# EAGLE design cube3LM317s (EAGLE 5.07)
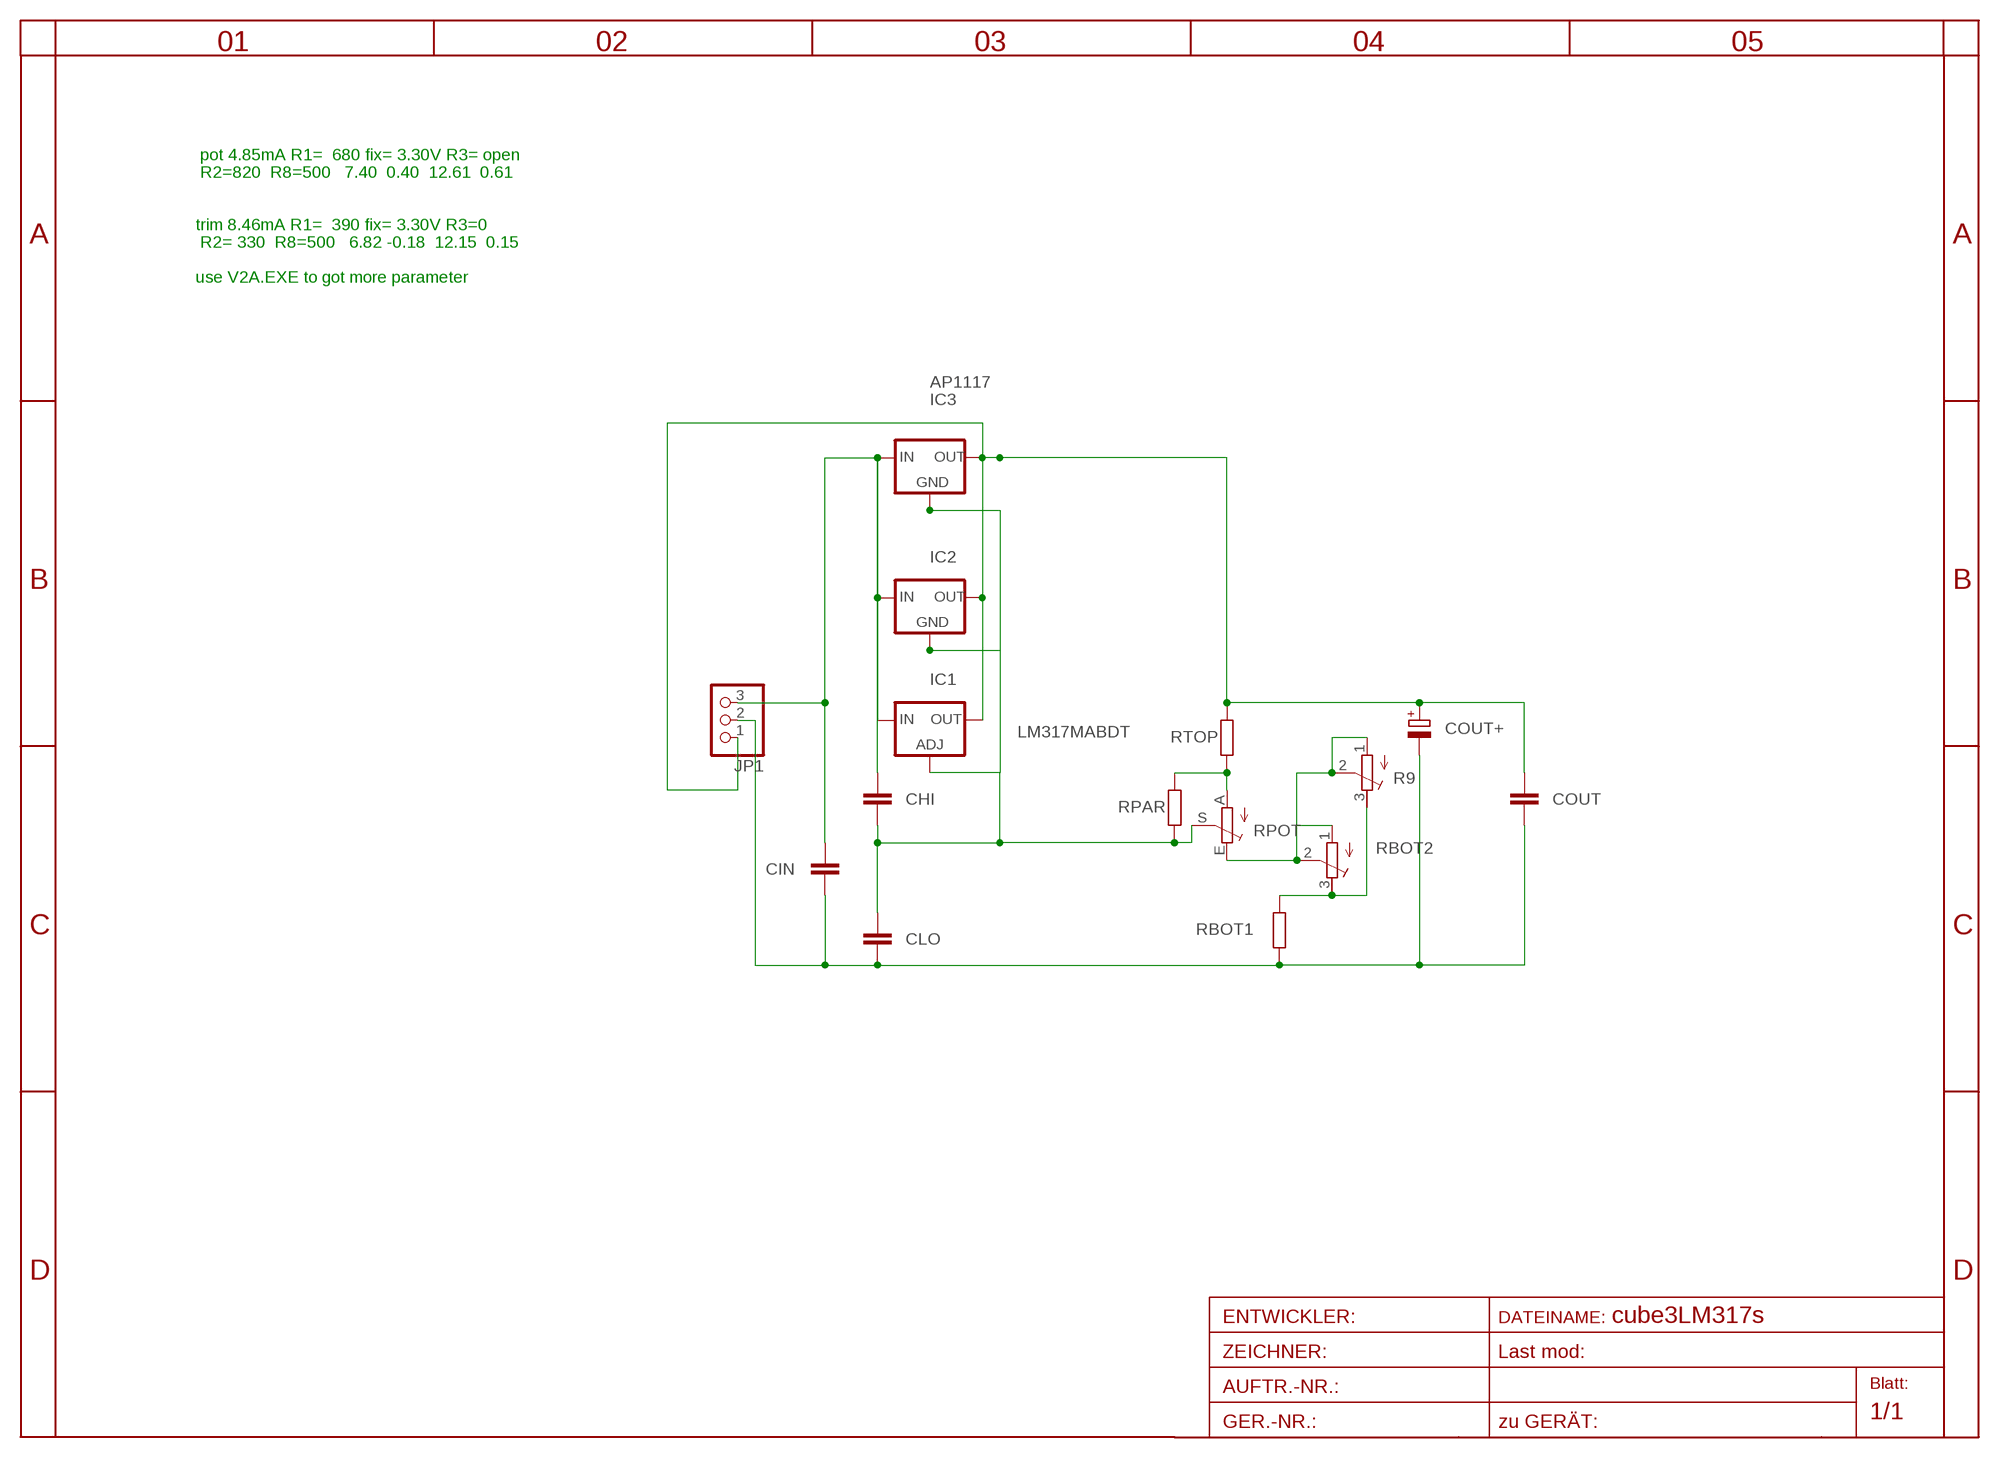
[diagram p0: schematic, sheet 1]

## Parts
CHI  C-EUC0805  [C0805]
CIN  C-EUC1206  [C1206]
CLO  C-EUC0805  [C0805]
COUT  C-EUC1206  [C1206]
COUT+  CPOL-EUE2.5-6  [E2,5-6]
IC1  LM317MABDT  [DPACK]
IC2  78XXS  [78XXS]
IC3  AP1117  [SOT223]
JP1  PINHD-1X3  [1X03]
R9  R-TRIMM3374  [RTRIM3374]
RBOT1  R-EU_R1206  [R1206]
RBOT2  R-TRIMM3202  [RTRIM3202]
RPAR  R-EU_R0603  [R0603]
RPOT  TRIM_EU-RAND160  [RANDL]
RTOP  R-EU_R0805  [R0805]

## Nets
GND: CIN.2 CLO.2 COUT+.- COUT.2 JP1.2 RBOT1.1
IN: CHI.1 CIN.1 IC1.3(IN) IC2.IN IC3.3(IN) JP1.3
N$1: R9.1(E) R9.2(S) RBOT2.1(E) RBOT2.2(S) RPOT.E
N$4: CHI.2 CLO.1 IC1.1(ADJ) IC2.GND IC3.1(GND) RPAR.1 RPOT.S
N$6: R9.3(A) RBOT1.2 RBOT2.3(A)
N$7: RPAR.2 RPOT.A RTOP.1
OUT: COUT+.+ COUT.1 IC1.4(OUT) IC2.OUT IC3.2(OUT) IC3.4(TAB) JP1.1 RTOP.2

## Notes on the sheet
- pot 4.85mA R1=  680 fix= 3.30V R3= open
- R2=820  R8=500   7.40  0.40  12.61  0.61
- trim 8.46mA R1=  390 fix= 3.30V R3=0
- R2= 330  R8=500   6.82 -0.18  12.15  0.15
- use V2A.EXE to got more parameter

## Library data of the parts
CHI CIN CLO COUT = rcl:C-EU: CAPACITOR, European symbol
COUT+ = rcl:CPOL-EU: POLARIZED CAPACITOR, European symbol
IC1 = v-reg:LM317?*: 500 mA Adjustable Output Positive Voltage Regulator Source: http://www.onsemi.co.jp .. LM317M-D.PDF
IC2 = v-reg:78XXS: VOLTAGE REGULATOR
IC3 = v-reg:AP1117
JP1 = pinhead:PINHD-1X3: PIN HEADER
R9 RBOT2 = rcl:R-TRIMM: Trimm resistor
RBOT1 RPAR RTOP = rcl:R-EU_: RESISTOR, European symbol
RPOT = pot:TRIM_EU-: POTENTIOMETER

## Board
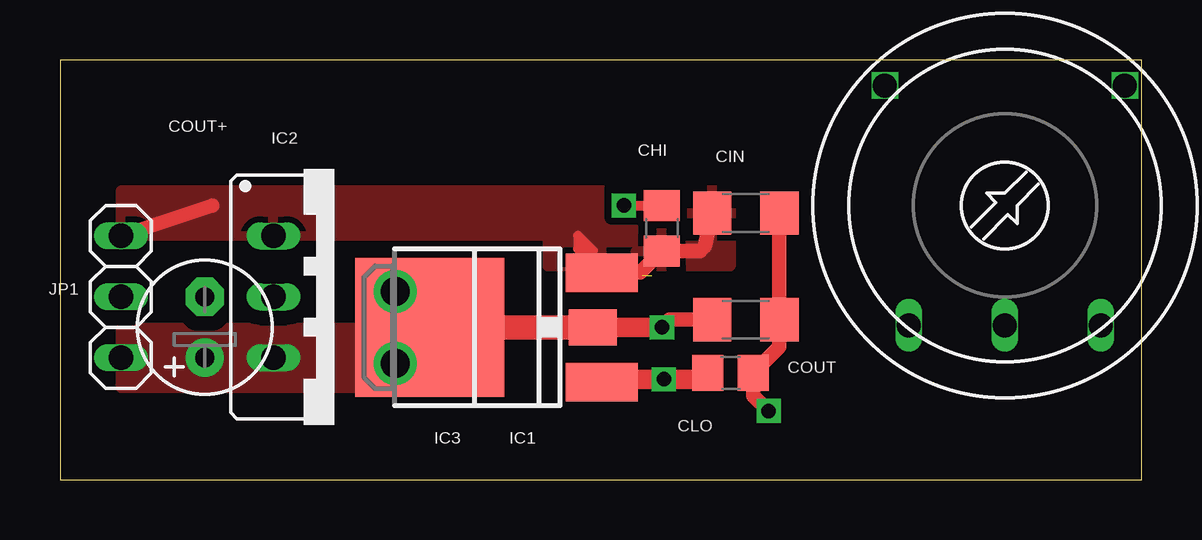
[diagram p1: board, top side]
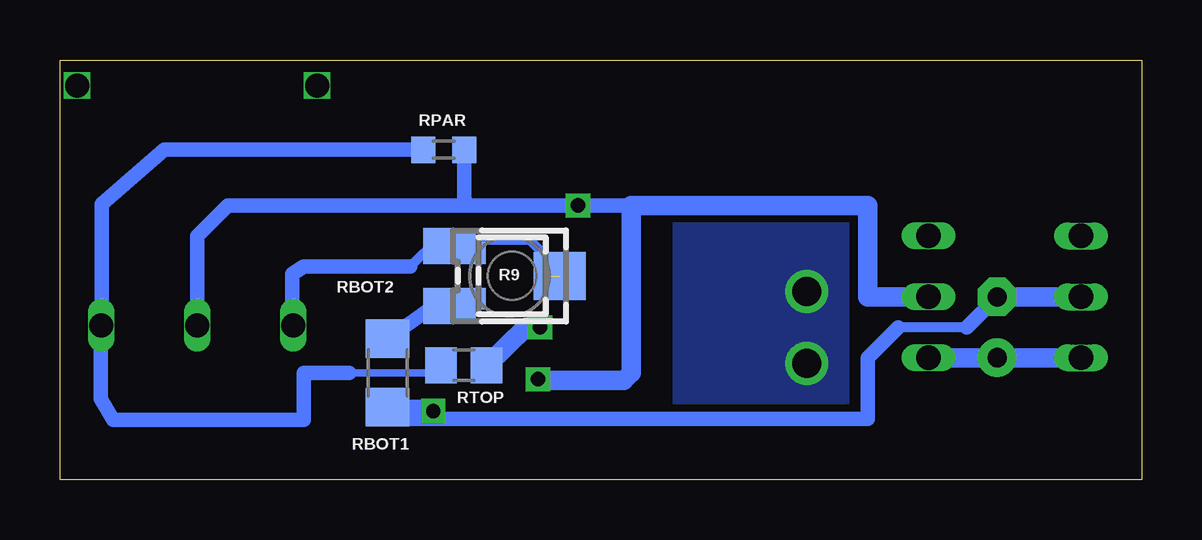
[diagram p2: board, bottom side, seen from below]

Size 45.08 x 17.5 mm. Coordinates in mm from the lower left corner, seen from the top.
Outline: 0,0 45.08,0 45.08,17.5 0,17.5 0,0
Copper layers (1*16): Top 0.035mm / dielectric 1.5mm / Bottom 0.035mm
Design rules "default": minimum track width 10mil, minimum drill 20mil, track to track 8mil, track to pad 8mil, pad to pad 8mil, via to via 8mil, smd to smd 8mil, copper to edge 40mil, drill to drill 8mil, minimum pad ring 1mil, minimum via ring 8mil, stop-mask expansion 4mil, vias tented up to drill 0mil, thermal gap 10mil

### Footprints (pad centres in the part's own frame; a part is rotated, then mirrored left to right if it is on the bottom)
C0805 = smd 1.3 x 1.5: 1 -0.95,0; 2 0.95,0
C1206 = smd 1.6 x 1.8: 1 -1.4,0; 2 1.4,0
E2,5-6 = drill 0.8 pad 1.6 round: + -1.27,0 | drill 0.8 pad 1.6 octagon: - 1.27,0
DPACK = smd 1.6 x 3: 1 -2.28,-4.8; 3 2.28,-4.8 | smd 5.8 x 6.2: 4 0,2.38
78XXS = drill 1.016 long: GND 0,-2.54; IN -2.54,-2.54; OUT 2.54,-2.54
SOT223 = smd 1.5 x 2: 1 -2.3,-3.15; 2 0,-3.15; 3 2.3,-3.15 | smd 3.8 x 2: 4 0,3.15
1X03 = drill 1.016 long: 1 -2.54,0; 2 0,0; 3 2.54,0
RTRIM3374 = smd 1.5 x 2.2: 1 -1.25,-2.5; 3 1.25,-2.5 | smd 1.98 x 2.17: 2 0,2.1
R1206 = smd 1.6 x 1.803: 1 -1.422,0; 2 1.422,0
RTRIM3202 = smd 0.9 x 1.3: 1 -0.95,-1.75; 3 0.95,-1.75 | smd 1.6 x 1.4: 2 0,1.6
R0603 = smd 1 x 1.1: 1 -0.85,0; 2 0.85,0
RANDL = drill 1 long: A -4,5; E 4,5; S 0,5 | drill 1 square: P$1 -5,-5; P$2 5,-5
R0805 = smd 1.3 x 1.5: 1 -0.95,0; 2 0.95,0

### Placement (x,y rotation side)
CHI  25.08,10.48 90 top
CIN  28.57,11.11 0 top
CLO  27.94,4.45 0 top
COUT  28.57,6.67 0 top
COUT+  6.03,6.35 90 top
IC1  17.78,6.35 90 top
IC2  11.43,7.62 270 top
IC3  19.05,6.35 90 top
JP1  2.54,7.62 90 top
R9  26.35,8.49 270 bottom
RBOT1  31.43,4.45 90 bottom
RBOT2  26.25,8.5 270 bottom
RPAR  29.09,13.76 180 bottom
RPOT  39.37,11.43 180 top
RTOP  28.26,4.76 0 bottom

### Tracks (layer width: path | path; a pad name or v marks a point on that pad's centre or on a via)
GND  (via drill 0.6)
  Top 0.61: CIN.2 COUT.2 29.98,5.53 CLO.2 28.89,3.5 v29.53,2.86
  Bottom 0.406: 7.3,6.35 10.16,6.35
  Bottom 0.61: 10.16,6.35 11.43,5.08 11.43,2.54 31.43,2.54 RBOT1.1 29.69,3.02 v29.53,2.86 | COUT+.- 7.3,6.35
  Bottom 0.813: JP1.2 COUT+.-
IN
  Top 0.406: 26.67,9.53 26.86,9.71 | CHI.1 | IC3.3 22.2,9.55 21.59,10.16 21.59,9.62 IC1.3
  Top 0.61: JP1.3 6.35,11.43 | IC1.3 24.18,8.63 CHI.1 | 26.86,9.71 CIN.1 | CHI.1 26.67,9.53
  Top 0.813: IC2.IN 8.26,10.16
  pour Top (isolate 0.305): 27.94,12.06 27.94,8.89 20.32,8.89 20.32,10.16 2.54,10.16 2.54,12.06
N$1  (1 unrouted)
  Bottom 0.406: RBOT2.2 24.65,9.15 25.5,10 28.55,10 | 28.59,10 R9.1 | 28.59,10 29.37,10 30.48,8.89 | 28.55,10 28.59,10 | 28.55,10 RBOT2.1
  Bottom 0.61: 30.48,8.89 34.92,8.89 35.41,8.57 35.41,6.62 RPOT.E
N$4  (via drill 0.6)
  Top 0.406: v23.5,11.43 CHI.2 | IC1.1 22.22,4.07 IC3.1
  Top 0.813: IC3.1 22.33,4.18 v25.16,4.18 26.93,4.18 CLO.1
  Bottom 0.61: 20.32,11.43 v23.5,11.43 28,11.43 | RPOT.S 39.37,10.16 38.1,11.43 28,11.43 | RPAR.1 28.24,11.67 28,11.43
  Bottom 0.813: IC2.GND 11.43,7.62 11.43,11.43 20.32,11.43 21.27,11.43 21.27,4.45 21.59,4.13 25.11,4.13 v25.16,4.18
N$6
  Bottom 0.406: R9.3 28.31,7.24 RBOT2.3
  Bottom 0.61: RBOT1.2 29.21,7.45 R9.3
N$7
  Bottom 0.305: 29.21,4.45 33.02,4.45
  Bottom 0.61: RTOP.1 29.21,4.45 | 33.02,4.45 34.92,4.45 34.92,2.49 42.86,2.49 43.38,3.36 43.38,5.79 RPOT.A 43.37,7.01 43.35,7.38 43.35,11.5 40.74,13.76 RPAR.2
OUT  (via drill 0.6, 1.2)
  Top 0.61: COUT.1 25.4,6.67 v25.08,6.35
  Top 0.813: IC3.2 v25.08,6.35
  Top 1.016: IC1.4 IC3.2
  Bottom 0.813: JP1.1 IC2.OUT | RTOP.2 25.67,6.35 v25.08,6.35
  other vias: 13.97,4.85 13.97,7.85
  pour Top (isolate 0.61, no thermals): 2.54,6.35 16.51,6.35 16.51,3.81 2.54,3.81
  pour Bottom (isolate 0.305): 19.37,11.1 19.37,3.17 12.38,3.17 12.38,10.79 12.06,11.1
